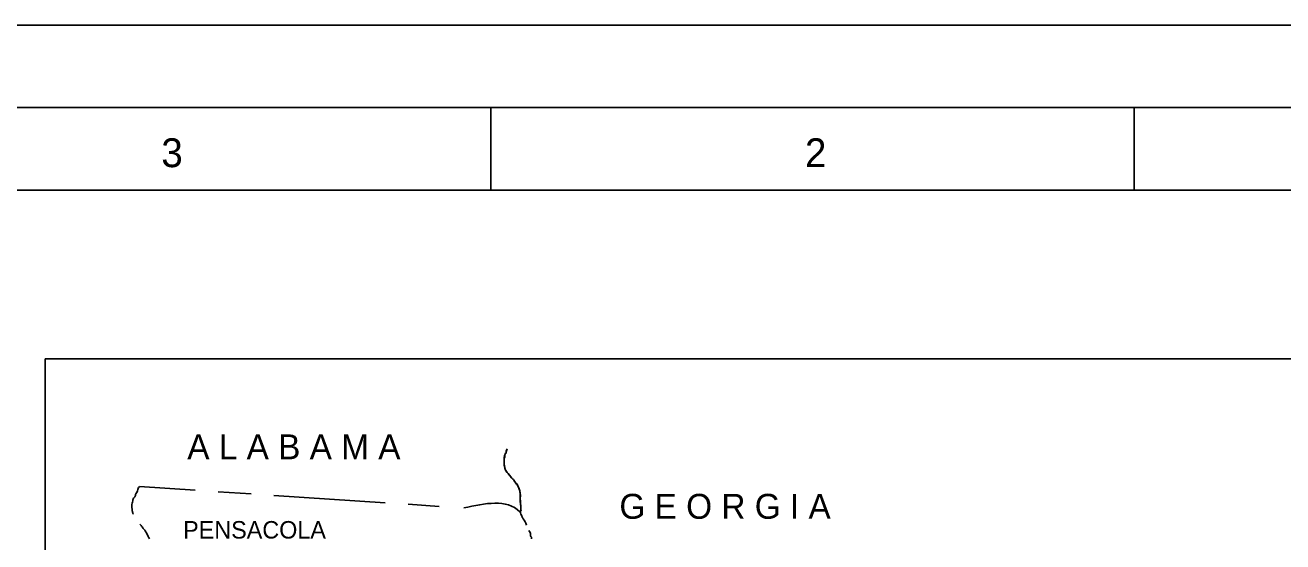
# Model space of a CAD drawing. Extents: x 452225 to 584229, y 1232161 to 1334160.
# Drawn here: x 542612 to 565476, y 1324758 to 1334160 of the extents above; entities that cross this region are included whole.
import ezdxf

# ---------------------------------------------------------------- set-up
doc = ezdxf.new("R2010")
doc.units = 0
for name, color, linetype in [('G-ANNO-NPLT', 7, 'Continuous'), ('G-ANNO-TTLB', 7, 'Continuous'), ('V-ANNO-SYMB', 7, 'Continuous')]:
    doc.layers.add(name, color=color, linetype=linetype)

msp = doc.modelspace()

# ---------------------------------------------------------------- linework, layer by layer
at = {"layer": 'G-ANNO-NPLT'}
msp.add_lwpolyline([(452225, 1334160), (584225, 1334160), (584225, 1232161), (452225, 1232161)], close=True, dxfattribs=at)
at = {"layer": 'G-ANNO-TTLB'}
for p, q in [((551075, 1332660), (551075, 1331160)), ((562775, 1332660), (562775, 1331160))]:
    msp.add_line(p, q, dxfattribs=at)
for points in [[(453725, 1233661), (582725, 1233661), (582725, 1332660), (453725, 1332660)], [(581225, 1331160), (457475, 1331160), (457475, 1235161), (581225, 1235161)]]:
    msp.add_lwpolyline(points, close=True, dxfattribs=at)
at = {"layer": 'V-ANNO-SYMB'}
for p, q in [((572610, 1328089), (542976, 1328089)), ((542976, 1328089), (542976, 1301350)), ((545704, 1325697), (544692, 1325765)), ((546720, 1325630), (546119, 1325671)), ((549159, 1325470), (547132, 1325603)), ((550136, 1325402), (549572, 1325442))]:
    msp.add_line(p, q, dxfattribs=at)
for points in [[(551629, 1325317), (551621, 1325358), (551621, 1325429), (551614, 1325511), (551614, 1325605), (551600, 1325699), (551574, 1325766), (551535, 1325824), (551479, 1325897), (551406, 1325985), (551349, 1326057), (551320, 1326148), (551322, 1326259), (551332, 1326341), (551357, 1326384), (551357, 1326406), (551377, 1326447)], [(551630, 1325314), (551624, 1325330), (551624, 1325403), (551613, 1325478), (551613, 1325619), (551603, 1325686), (551578, 1325756), (551535, 1325827), (551519, 1325843), (551487, 1325891), (551449, 1325929), (551400, 1325994), (551365, 1326032), (551333, 1326099), (551322, 1326159), (551322, 1326240), (551327, 1326288), (551333, 1326307), (551338, 1326356), (551354, 1326383), (551360, 1326415), (551376, 1326448)], [(544692, 1325765), (544673, 1325747), (544661, 1325711), (544649, 1325668), (544624, 1325635), (544615, 1325601), (544603, 1325578), (544592, 1325567), (544568, 1325505), (544556, 1325460), (544550, 1325413), (544555, 1325354), (544565, 1325296), (544571, 1325276), (544578, 1325261)], [(551729, 1325065), (551667, 1325180), (551655, 1325194), (551647, 1325206), (551643, 1325227), (551626, 1325260), (551608, 1325305), (551606, 1325307), (550589, 1325376)], [(544695, 1325080), (544730, 1325046), (544752, 1325012), (544785, 1324971), (544823, 1324910), (544840, 1324872), (544873, 1324812)], [(551818, 1324816), (551816, 1324843), (551798, 1324867), (551800, 1324894), (551767, 1324963)]]:
    msp.add_spline(points, degree=3, dxfattribs=at)

# ---------------------------------------------------------------- texts
at = {"layer": 'G-ANNO-TTLB'}
for s, p in [('3', (545087, 1331576)), ('2', (556788, 1331576))]:
    msp.add_text(s, height=525, dxfattribs=at).set_placement(p)
at = {"layer": 'V-ANNO-SYMB'}
for s, height, p in [('A L A B A M A', 453.6, (545559, 1326261)), ('G E O R G I A', 453.6, (553415, 1325178)), ('PENSACOLA', 317.5, (545484, 1324819))]:
    msp.add_text(s, height=height, rotation=0, dxfattribs=at).set_placement(p)

doc.saveas('drawing.dxf')
